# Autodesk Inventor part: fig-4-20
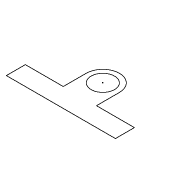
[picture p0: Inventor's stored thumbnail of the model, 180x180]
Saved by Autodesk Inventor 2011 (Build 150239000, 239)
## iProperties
Created: 2004-05
Part Number: fig-4-20
Document SubType Name: Modeling
Designer: CADCIM Technologies
Manufacturer: Standard
Standards Organization: Custom
Density: 1 g/cm^3
Author: CADCIM Technologies
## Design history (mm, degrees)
sketch "Sketch1"
  geometry: L1 (21.396, 25)-(21.396, 15.181); L2 (21.396, 15.181)-(77.829, 15.181); L3 (77.829, 15.181)-(77.829, 25); L4 (77.829, 25)-(58.204, 25); L5 (58.204, 25)-(58.204, 36.886); L6 (41.021, 36.886)-(41.021, 25); L7 (41.021, 25)-(21.396, 25); C1 r 6.072 at (49.612, 36.886); A1 r 8.592 centre (49.612, 36.886) between (58.204, 36.886) and (41.021, 36.886)
  constraints: 14 end point, 5 parallel, 2 centre point, 2 equal length, 2 point on circle, 2 tangent, 1 coincident, 1 perpendicular, 1 vertical, 1 other
